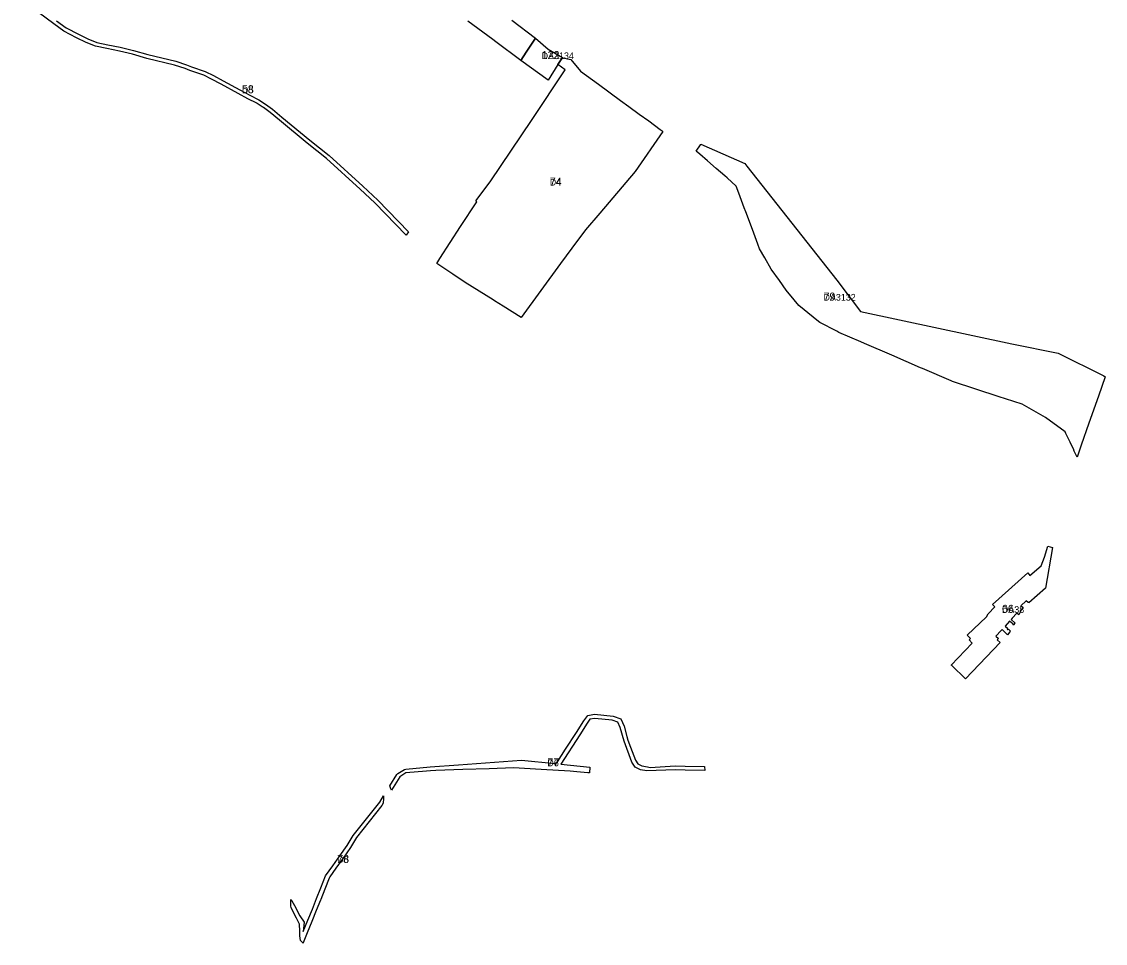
# Model space of a CAD drawing. Extents: x -537012 to -534603, y -1176562 to -1172739.
# Drawn here: x -535946 to -535134, y -1176562 to -1175871 of the extents above; entities that cross this region are included whole.
import ezdxf

# ---------------------------------------------------------------- set-up
doc = ezdxf.new("R2010")
doc.units = 0
for name, color, linetype in [('96120023', 7, 'Continuous'), ('96140023', 7, 'Continuous'), ('ID_VPO', 7, 'Continuous'), ('ID_VPS', 7, 'Continuous')]:
    doc.layers.add(name, color=color, linetype=linetype)

msp = doc.modelspace()

# ---------------------------------------------------------------- linework, layer by layer
at = {"layer": '96120023'}
msp.add_lwpolyline([(-535919.82, -1175870.67), (-535912.56, -1175875.93), (-535903.3, -1175880.69), (-535896.35, -1175884.13), (-535889.59, -1175886.88), (-535881.33, -1175888.64), (-535871.94, -1175890.51), (-535862.05, -1175892.89), (-535851.29, -1175896.02), (-535830.38, -1175901.03), (-535822.37, -1175903.66), (-535818.62, -1175905.16), (-535808.23, -1175908.79), (-535802.09, -1175911.79), (-535794.89, -1175915.67), (-535782.25, -1175922.56), (-535774.87, -1175926.44), (-535768.11, -1175929.95), (-535762.97, -1175933.33), (-535757.72, -1175936.96), (-535750.71, -1175942.84), (-535729.93, -1175960.24), (-535715.4, -1175971.76), (-535690.12, -1175994.66), (-535678.91, -1176005.05), (-535655.86, -1176028.92), (-535657.54, -1176031.49), (-535681.02, -1176007.2), (-535692.15, -1175996.87), (-535717.35, -1175974.04), (-535731.82, -1175962.56), (-535752.63, -1175945.14), (-535759.54, -1175939.34), (-535764.65, -1175935.81), (-535765.54, -1175935.22), (-535769.33, -1175932.73), (-535769.62, -1175932.54), (-535776.25, -1175929.1), (-535783.67, -1175925.2), (-535796.32, -1175918.31), (-535803.46, -1175914.46), (-535809.38, -1175911.56), (-535819.67, -1175907.97), (-535823.4, -1175906.48), (-535831.2, -1175903.92), (-535852.06, -1175898.92), (-535862.82, -1175895.79), (-535872.59, -1175893.44), (-535881.94, -1175891.57), (-535890.48, -1175889.76), (-535897.59, -1175886.87), (-535904.65, -1175883.37), (-535914.14, -1175878.49), (-535921.6, -1175873.09), (-535945.82, -1175855.15)], dxfattribs=at)
for points in [[(-535540.36, -1175898.34), (-535540.29, -1175898.38), (-535534.34, -1175899.65), (-535526.89, -1175908.36), (-535513.42, -1175918.29), (-535497.01, -1175930.38), (-535490.65, -1175935.04), (-535482.99, -1175940.63), (-535475.88, -1175945.79), (-535467.26, -1175952.11), (-535465.65, -1175953.29), (-535465.28, -1175953.69), (-535485.92, -1175983.59), (-535512.53, -1176014.91), (-535523.23, -1176027.37), (-535533.43, -1176041.1), (-535542.01, -1176052.66), (-535571.42, -1176093.12), (-535584.91, -1176084.6), (-535591.35, -1176080.53), (-535592.48, -1176079.84), (-535613.52, -1176066.99), (-535622.74, -1176060.73), (-535634.73, -1176052.58), (-535632.36, -1176048.86), (-535617.03, -1176024.82), (-535604.62, -1176006.3), (-535605.36, -1176005.77), (-535594.65, -1175991.42), (-535563.27, -1175944.59), (-535538.46, -1175907.57), (-535543.85, -1175903.41)], [(-535492.23, -1176407.19), (-535491.5, -1176409.86), (-535489.51, -1176415.24), (-535485.87, -1176425.04), (-535483.96, -1176427.79), (-535480.98, -1176429.21), (-535476.78, -1176430.03), (-535474.65, -1176430.44), (-535456.08, -1176429.16), (-535448.49, -1176429.32), (-535433.95, -1176429.62), (-535433.67, -1176432.62), (-535448.55, -1176432.32), (-535456, -1176432.17), (-535477.35, -1176432.97), (-535481.93, -1176432.09), (-535485.97, -1176430.15), (-535488.55, -1176426.44), (-535494.36, -1176410.78), (-535497.18, -1176400.37), (-535499.04, -1176396.42), (-535503.24, -1176394.88), (-535516.31, -1176393.59), (-535519.86, -1176394.24), (-535522.04, -1176397.14), (-535527.53, -1176405.86), (-535541.79, -1176427.98), (-535519.96, -1176430.27), (-535520.14, -1176434.4), (-535521.58, -1176434.42), (-535529.7, -1176433.67), (-535534.68, -1176433.18), (-535556.56, -1176431.9), (-535577.27, -1176430.68), (-535595.45, -1176431.32), (-535615.18, -1176432.01), (-535635.36, -1176432.72), (-535639.44, -1176432.86), (-535642.39, -1176433.18), (-535657.92, -1176434.41), (-535662.5, -1176437.48), (-535668.75, -1176447.51), (-535669.15, -1176446.4), (-535669.94, -1176444.21), (-535664.74, -1176435.61), (-535663.81, -1176434.93), (-535658.77, -1176432.03), (-535657.85, -1176431.79), (-535639.55, -1176429.82), (-535618.53, -1176428.31), (-535571.1, -1176424.91), (-535546.07, -1176427.53), (-535544.12, -1176426.06), (-535538.13, -1176416.77), (-535530.06, -1176404.25), (-535524.51, -1176395.44), (-535521.55, -1176391.5), (-535516.43, -1176390.57), (-535502.56, -1176391.94), (-535496.85, -1176394.02), (-535494.36, -1176399.33)], [(-535674.59, -1176451.72), (-535674.67, -1176453.74), (-535674.81, -1176457.22), (-535675.87, -1176458.92), (-535694.78, -1176482.86), (-535699.45, -1176490.49), (-535704.9, -1176498.43), (-535705.52, -1176499.3), (-535710.34, -1176505.96), (-535714.92, -1176512.29), (-535715.34, -1176513.34), (-535718.6, -1176521.51), (-535721.7, -1176529.29), (-535721.93, -1176529.86), (-535725.02, -1176537.6), (-535728.31, -1176545.84), (-535731.73, -1176554.4), (-535734.72, -1176561.9), (-535734.85, -1176562.23), (-535735.32, -1176561.72), (-535736.89, -1176560.03), (-535737.27, -1176556.72), (-535737.4, -1176552.99), (-535737.57, -1176547.8), (-535739.84, -1176543.43), (-535743.9, -1176535.62), (-535743.96, -1176534.12), (-535744.12, -1176529.72), (-535743.81, -1176529.37), (-535743.29, -1176530.39), (-535741.44, -1176533.9), (-535737.41, -1176541.67), (-535734.17, -1176546.44), (-535734.75, -1176553.24), (-535731.3, -1176544.75), (-535727.94, -1176536.52), (-535724.82, -1176528.73), (-535721.59, -1176520.75), (-535718.01, -1176511.69), (-535712.69, -1176504.06), (-535707.35, -1176496.57), (-535701.92, -1176488.79), (-535697.41, -1176481.4), (-535677.45, -1176456.39)]]:
    msp.add_lwpolyline(points, close=True, dxfattribs=at)
at = {"layer": '96140023'}
msp.add_lwpolyline([(-535578.42, -1175870.31), (-535560.76, -1175883.69), (-535567.74, -1175894.34), (-535571.74, -1175900.46), (-535590.32, -1175886.38), (-535592.65, -1175884.69), (-535611.42, -1175871.09)], dxfattribs=at)
for points in [[(-535571.74, -1175900.46), (-535567.74, -1175894.34), (-535560.76, -1175883.69), (-535551.25, -1175892.1), (-535540.36, -1175898.34), (-535543.85, -1175903.41), (-535551.3, -1175915.16)], [(-535160.02, -1176186.67), (-535163.15, -1176180), (-535163.75, -1176178.72), (-535178.52, -1176168.01), (-535196.01, -1176158.19), (-535208.54, -1176154.09), (-535213.22, -1176152.56), (-535248.07, -1176141.17), (-535248.23, -1176141.12), (-535249.25, -1176140.68), (-535270.7, -1176131.4), (-535272.14, -1176130.78), (-535293.74, -1176121.44), (-535314.01, -1176112.68), (-535316.8, -1176111.47), (-535333.44, -1176104.28), (-535334.8, -1176103.36), (-535347.64, -1176096.92), (-535349.8, -1176095.16), (-535359.23, -1176087.47), (-535363.21, -1176084.23), (-535366.75, -1176079.98), (-535372.8, -1176072.73), (-535377.89, -1176065.42), (-535383.95, -1176056.8), (-535388.88, -1176048.37), (-535392.88, -1176041.53), (-535394.14, -1176038.1), (-535398.17, -1176027.18), (-535403.12, -1176013.79), (-535404.21, -1176010.83), (-535408.25, -1175999.88), (-535410.18, -1175994.65), (-535417.16, -1175988.54), (-535418.91, -1175987.01), (-535425.27, -1175981.45), (-535431.84, -1175975.7), (-535437.53, -1175970.72), (-535440.26, -1175968.33), (-535437.02, -1175963.6), (-535436.86, -1175963.37), (-535436.69, -1175963.12), (-535403.85, -1175977.64), (-535402.23, -1175979.7), (-535334.93, -1176065.14), (-535317.12, -1176088.61), (-535203.59, -1176112.91), (-535169.04, -1176119.86), (-535134.66, -1176136.96), (-535133.61, -1176137.48), (-535138.79, -1176152.2), (-535145.91, -1176172.43), (-535151.7, -1176188.89), (-535153.49, -1176193.96), (-535154.82, -1176197.75), (-535156.89, -1176193.35), (-535157.31, -1176192.45), (-535157.32, -1176192.43)], [(-535178.34, -1176296.11), (-535190.94, -1176306.89), (-535191.27, -1176306.54), (-535191.55, -1176306.8), (-535192.88, -1176305.39), (-535196.99, -1176309.23), (-535195.45, -1176310.76), (-535196.19, -1176311.39), (-535198.46, -1176316.05), (-535199.98, -1176314.7), (-535203.41, -1176318.45), (-535204.15, -1176319.41), (-535201.38, -1176321.9), (-535202.24, -1176323.62), (-535202.93, -1176322.83), (-535205.38, -1176320.67), (-535208.78, -1176324.43), (-535206.8, -1176326.22), (-535207.27, -1176326.74), (-535206.82, -1176327.14), (-535206.35, -1176326.62), (-535205.83, -1176327.09), (-535204.6, -1176328.27), (-535205.13, -1176328.84), (-535207.02, -1176330.88), (-535211.04, -1176327.08), (-535211.77, -1176327.8), (-535215.69, -1176332), (-535213.78, -1176333.79), (-535214.58, -1176334.63), (-535212.46, -1176336.63), (-535238.41, -1176364.03), (-535248.77, -1176353.91), (-535249.05, -1176353.64), (-535233.47, -1176337.17), (-535235.74, -1176334.73), (-535234.76, -1176333.79), (-535237.17, -1176331.26), (-535222.74, -1176317.47), (-535221.32, -1176315.27), (-535216.38, -1176310.11), (-535218.13, -1176308.14), (-535191.79, -1176284.58), (-535190.07, -1176286.5), (-535181.65, -1176279.3), (-535179.27, -1176272.74), (-535176.74, -1176264.58), (-535173.21, -1176265.45)]]:
    msp.add_lwpolyline(points, close=True, dxfattribs=at)

# ---------------------------------------------------------------- texts
at = {"layer": '96120023'}
for s, rotation, p in [('D5', 360, (-535780.78, -1175925.02)), ('D4', 0, (-535550, -1175994.23)), ('D6', 360, (-535551.81, -1176429.55)), ('D6', 0, (-535709.36, -1176501.99))]:
    msp.add_text(s, height=5, rotation=rotation, dxfattribs=at).set_placement(p)
at = {"layer": '96140023'}
for s, p in [('DA3134', (-535556.09, -1175899.43)), ('DA3132', (-535344.85, -1176080.44)), ('DA38', (-535211.13, -1176314.52))]:
    msp.add_text(s, height=5, rotation=0, dxfattribs=at).set_placement(p)
at = {"layer": 'ID_VPO'}
for s, p in [('122', (-535556.09, -1175899.43)), ('79', (-535344.85, -1176080.44)), ('66', (-535211.13, -1176314.52))]:
    msp.add_text(s, height=6, rotation=0, dxfattribs=at).set_placement(p)
at = {"layer": 'ID_VPS'}
for s, rotation, p in [('58', 360, (-535780.78, -1175925.02)), ('74', 0, (-535550, -1175994.23)), ('77', 360, (-535551.81, -1176429.55)), ('78', 0, (-535709.36, -1176501.99))]:
    msp.add_text(s, height=6, rotation=rotation, dxfattribs=at).set_placement(p)

doc.saveas('drawing.dxf')
